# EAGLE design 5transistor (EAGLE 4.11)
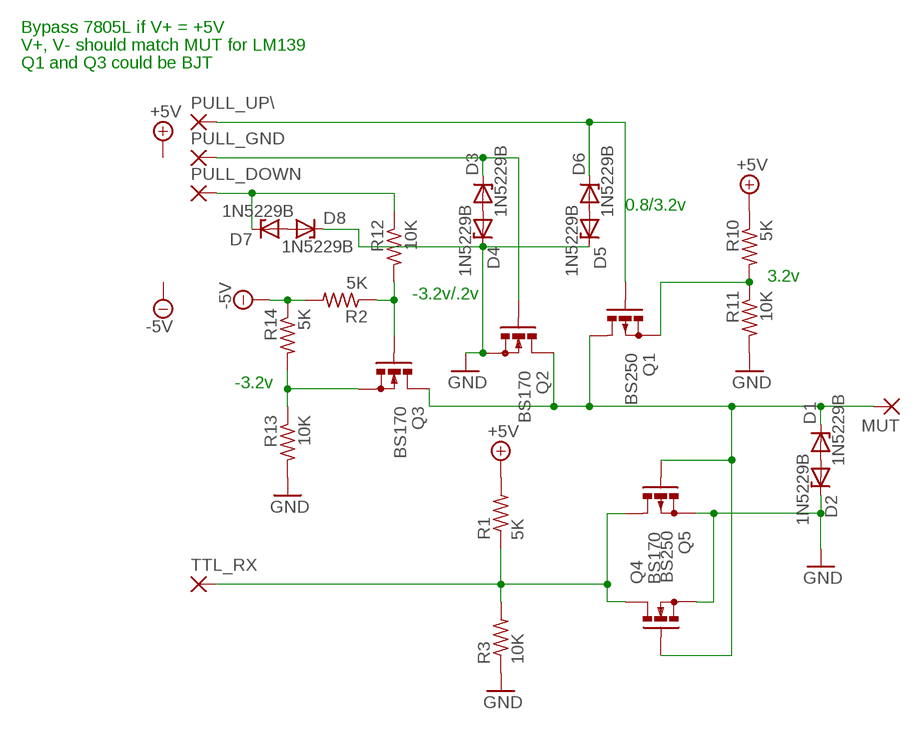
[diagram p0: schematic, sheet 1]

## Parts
D1  1N5229B  ZENER-DIODEZD-2.5  [ZDIO-2.5]
D2  1N5229B  ZENER-DIODEZD-2.5  [ZDIO-2.5]
D3  1N5229B  ZENER-DIODEZD-2.5  [ZDIO-2.5]
D4  1N5229B  ZENER-DIODEZD-2.5  [ZDIO-2.5]
D5  1N5229B  ZENER-DIODEZD-2.5  [ZDIO-2.5]
D6  1N5229B  ZENER-DIODEZD-2.5  [ZDIO-2.5]
D7  1N5229B  ZENER-DIODEZD-2.5  [ZDIO-2.5]
D8  1N5229B  ZENER-DIODEZD-2.5  [ZDIO-2.5]
MUT  1,6/0,9  [1,6/0,9]
PULL_DOWN  1,6/0,9  [1,6/0,9]
PULL_GND  1,6/0,9  [1,6/0,9]
PULL_UP\  1,6/0,9  [1,6/0,9]
Q1  BS250  [SOT54E]
Q2  BS170  [SOT54E]
Q3  BS170  [SOT54E]
Q4  BS170  [SOT54E]
Q5  BS250  [SOT54E]
R1  5K  R-US_0207/2V  [0207/2V]
R2  5K  R-US_0207/2V  [0207/2V]
R3  10K  R-US_0207/2V  [0207/2V]
R10  5K  R-US_0207/2V  [0207/2V]
R11  10K  R-US_0207/2V  [0207/2V]
R12  10K  R-US_0207/2V  [0207/2V]
R13  10K  R-US_0207/2V  [0207/2V]
R14  5K  R-US_0207/2V  [0207/2V]
TTL_RX  1,6/0,9  [1,6/0,9]

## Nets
+5V: R1.2 R10.1
-5V: R2.2 R14.1
GND: D2.C D4.C D5.C D8.C Q2.S Q4.S Q5.S R3.1 R11.2 R13.2
N$1: D1.C MUT.1(P) Q1.D Q2.D Q3.D Q4.G Q5.G
N$2: Q3.G R2.1 R12.2
N$3: D3.C PULL_GND.1(P) Q2.G
N$4: D7.C PULL_DOWN.1(P) R12.1
N$5: Q1.S R10.2 R11.1
N$6: D5.A D6.A
N$7: D1.A D2.A
N$8: Q4.D Q5.D R1.1 R3.2 TTL_RX.1(P)
N$10: D6.C PULL_UP\.1(P) Q1.G
N$11: D3.A D4.A
N$15: D7.A D8.A
N$16: Q3.S R13.1 R14.2

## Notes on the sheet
- Bypass 7805L if V+ = +5V
- V+, V- should match MUT for LM139
- Q1 and Q3 could be BJT
- 0.8/3.2v
- 3.2v
- -3.2v/.2v
- -3.2v

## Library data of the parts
D1-D8 = diode:ZENER-DIODE: Z-Diode
MUT PULL_DOWN PULL_GND PULL_UP\ TTL_RX = wirepad:1,6/0,9: THROUGH-HOLE PAD
Q1 Q5 = transistor-small-signal:BS250: P-CHANNEL MOS FET
Q2-Q4 = transistor-small-signal:BS170: N-CHANNEL MOS FET
R1-R3 R10-R14 = rcl:R-US_: RESISTOR, American symbol

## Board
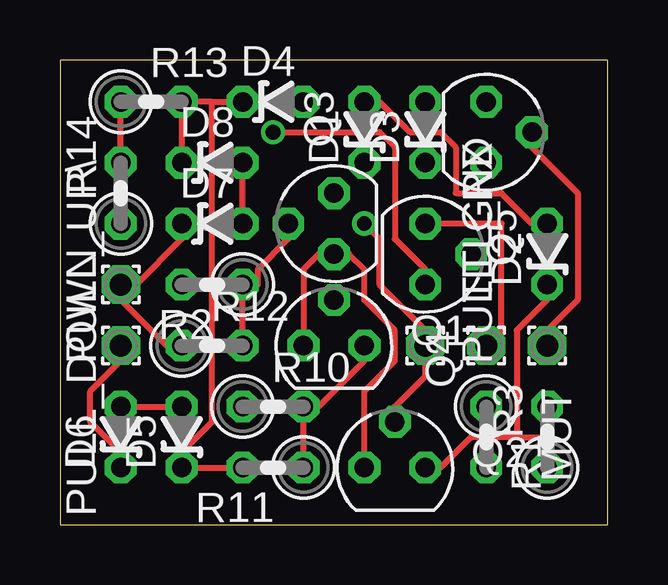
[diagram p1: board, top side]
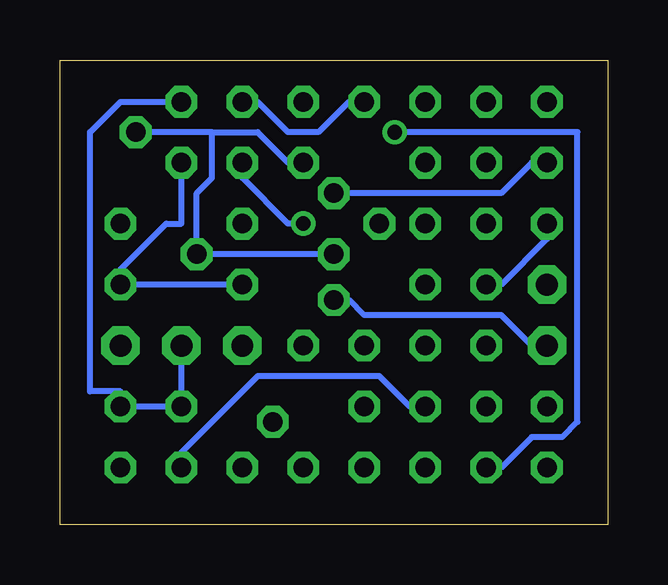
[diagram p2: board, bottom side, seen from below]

Size 22.84 x 19.36 mm. Coordinates in mm from the lower left corner, seen from the top.
Outline: 0,0 22.84,0 22.84,19.36 0,19.36 0,0
Copper layers (1*16): Top 0.035mm / dielectric 1.5mm / Bottom 0.035mm
Design rules "default": minimum track width 10mil, minimum drill 24mil, track to track 8mil, track to pad 8mil, pad to pad 8mil, via to via 8mil, smd to smd 8mil, copper to edge 40mil, drill to drill 8mil, minimum pad ring 10mil, minimum via ring 8mil, stop-mask expansion 4mil, vias tented up to drill 0mil, thermal gap 10mil

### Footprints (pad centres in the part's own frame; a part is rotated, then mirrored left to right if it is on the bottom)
ZDIO-2.5 = drill 0.813 octagon: A 1.27,0; C -1.27,0
1,6/0,9 = drill 0.914 pad 1.6 octagon: 1 0,0
SOT54E = drill 0.813 octagon: D -1.27,0; G 0,1.905; S 1.27,0
0207/2V = drill 0.813 octagon: 1 -1.27,0; 2 1.27,0

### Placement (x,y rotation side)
D1  12.69,16.35 90 top
D2  20.32,11.27 90 top
D3  15.23,16.35 90 top
D4  8.88,17.62 0 top
D5  5.08,3.65 90 top
D6  2.54,3.65 90 top
D7  6.34,12.54 0 top
D8  6.34,15.08 0 top
MUT  20.32,7.46 270 top
PULL_DOWN  2.54,10 270 top
PULL_GND  15.23,7.46 0 top
PULL_UP\  2.54,7.46 90 top
Q1  11.42,7.46 0 top
Q2  13.96,2.38 0 top
Q3  11.42,12.54 90 top
Q4  15.23,11.27 270 top
Q5  17.78,16.35 270 top
R1  17.78,3.65 270 top
R2  6.34,10 180 top
R3  20.32,3.65 90 top
R10  8.88,4.92 0 top
R11  8.88,2.38 180 top
R12  6.34,7.46 0 top
R13  3.81,17.62 0 top
R14  2.54,13.81 90 top
TTL_RX  17.78,7.46 90 top

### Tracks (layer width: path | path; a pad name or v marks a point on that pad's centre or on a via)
+5V
  Bottom 0.254: R1.2 17.78,3.01 14.6,6.18 9.52,6.18 8.25,4.92 R10.1
-5V
  Bottom 0.254: R14.1 2.54,11.9 4.44,10 R2.2
GND  (via drill 0.61)
  Top 0.254: R11.2 6.98,2.38 5.71,2.38 D5.C 5.08,3.01 6.34,4.28 6.34,17.62 | D8.C 5.08,15.71 5.08,16.98 R13.2 5.71,17.62 6.34,17.62 | 6.34,17.62 6.98,17.62 D4.C | 19.05,3.65 20.32,3.65 20.32,3.01 R3.1 | 19.05,3.65 17.14,3.65 15.87,2.38 Q2.S | 19.05,3.65 19.05,8.09 20.32,9.36 D2.C | v8.88,16.35 13.33,16.35 13.96,15.71 13.96,11.9 15.23,10.63 Q4.S
  Bottom 0.254: Q4.S 15.87,10 19.68,10 D2.C 20.32,10.63 18.41,12.54 17.78,12.54 17.78,14.44 Q5.S | v8.88,16.35 1.27,16.35 1.27,4.28 1.9,3.65 3.17,3.65 4.44,2.38 D5.C
N$1
  Top 0.254: Q1.D 10.15,8.09 10.15,10.63 10.79,11.27 Q3.D 12.06,11.27 12.69,10.63 12.69,9.36 13.96,8.09 13.96,6.82 12.69,5.55 12.69,3.01 Q2.D | MUT.1 20.32,8.09 21.59,9.36 21.59,13.81 19.68,15.71 Q5.G
  Bottom 0.254: Q3.D 12.06,11.27 16.51,11.27 Q4.G 17.14,11.9 17.14,13.81 16.51,14.44 16.51,16.35 | 16.51,16.35 19.05,16.35 Q5.G | 16.51,16.35 14.6,16.35 13.33,15.08 D1.C
N$2
  Top 0.254: R12.2 7.62,8.09 7.62,9.36 R2.1 8.25,10 8.25,10.63 9.52,11.9 Q3.G
N$3  (via drill 0.61)
  Top 0.254: Q2.G 13.96,4.92 15.23,6.18 15.23,6.82 PULL_GND.1 15.23,8.09 13.33,10 13.33,11.9 v12.69,12.54
  Bottom 0.254: v12.69,12.54 13.33,12.54 15.23,14.44 D3.C
N$4
  Top 0.254: R12.1 4.44,7.46 2.54,9.36 PULL_DOWN.1 3.17,10 5.08,11.9 D7.C
N$5
  Top 0.254: R11.1 10.15,3.01 10.15,4.28 R10.2 10.79,4.92 12.69,6.82 Q1.S
N$6
  Top 0.254: D6.A 3.17,4.92 4.44,4.92 D5.A
N$7
  Top 0.254: D2.A 19.68,12.54 18.41,13.81 16.51,13.81 16.51,15.71 15.87,16.35 14.6,16.35 13.33,17.62 D1.A
N$8
  Top 0.254: Q4.D 15.87,12.54 18.41,12.54 18.41,7.46 TTL_RX.1
  Bottom 0.254: Q5.D 18.41,17.62 20.32,17.62 21.59,16.35 21.59,5.55 20.32,5.55 R3.2 19.68,4.92 18.41,4.92 R1.1 17.78,5.55 17.78,6.82 TTL_RX.1
N$10
  Top 0.254: D6.C 2.54,3.01 1.27,4.28 1.27,5.55 2.54,6.82 PULL_UP\.1
  Bottom 0.254: Q1.G 10.79,9.36 10.15,8.73 4.44,8.73 3.17,7.46 PULL_UP\.1
N$11
  Bottom 0.254: D4.A 10.79,17.62 12.06,16.35 13.33,16.35 14.6,17.62 D3.A
N$15
  Top 0.254: D7.A 7.62,13.17 7.62,14.44 D8.A
N$16
  Top 0.254: R14.2 2.54,15.71 2.54,16.98 R13.1
  Bottom 0.254: Q3.S 10.79,13.81 4.44,13.81 3.17,15.08 R14.2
